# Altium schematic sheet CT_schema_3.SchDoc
size 300 x 247 mm
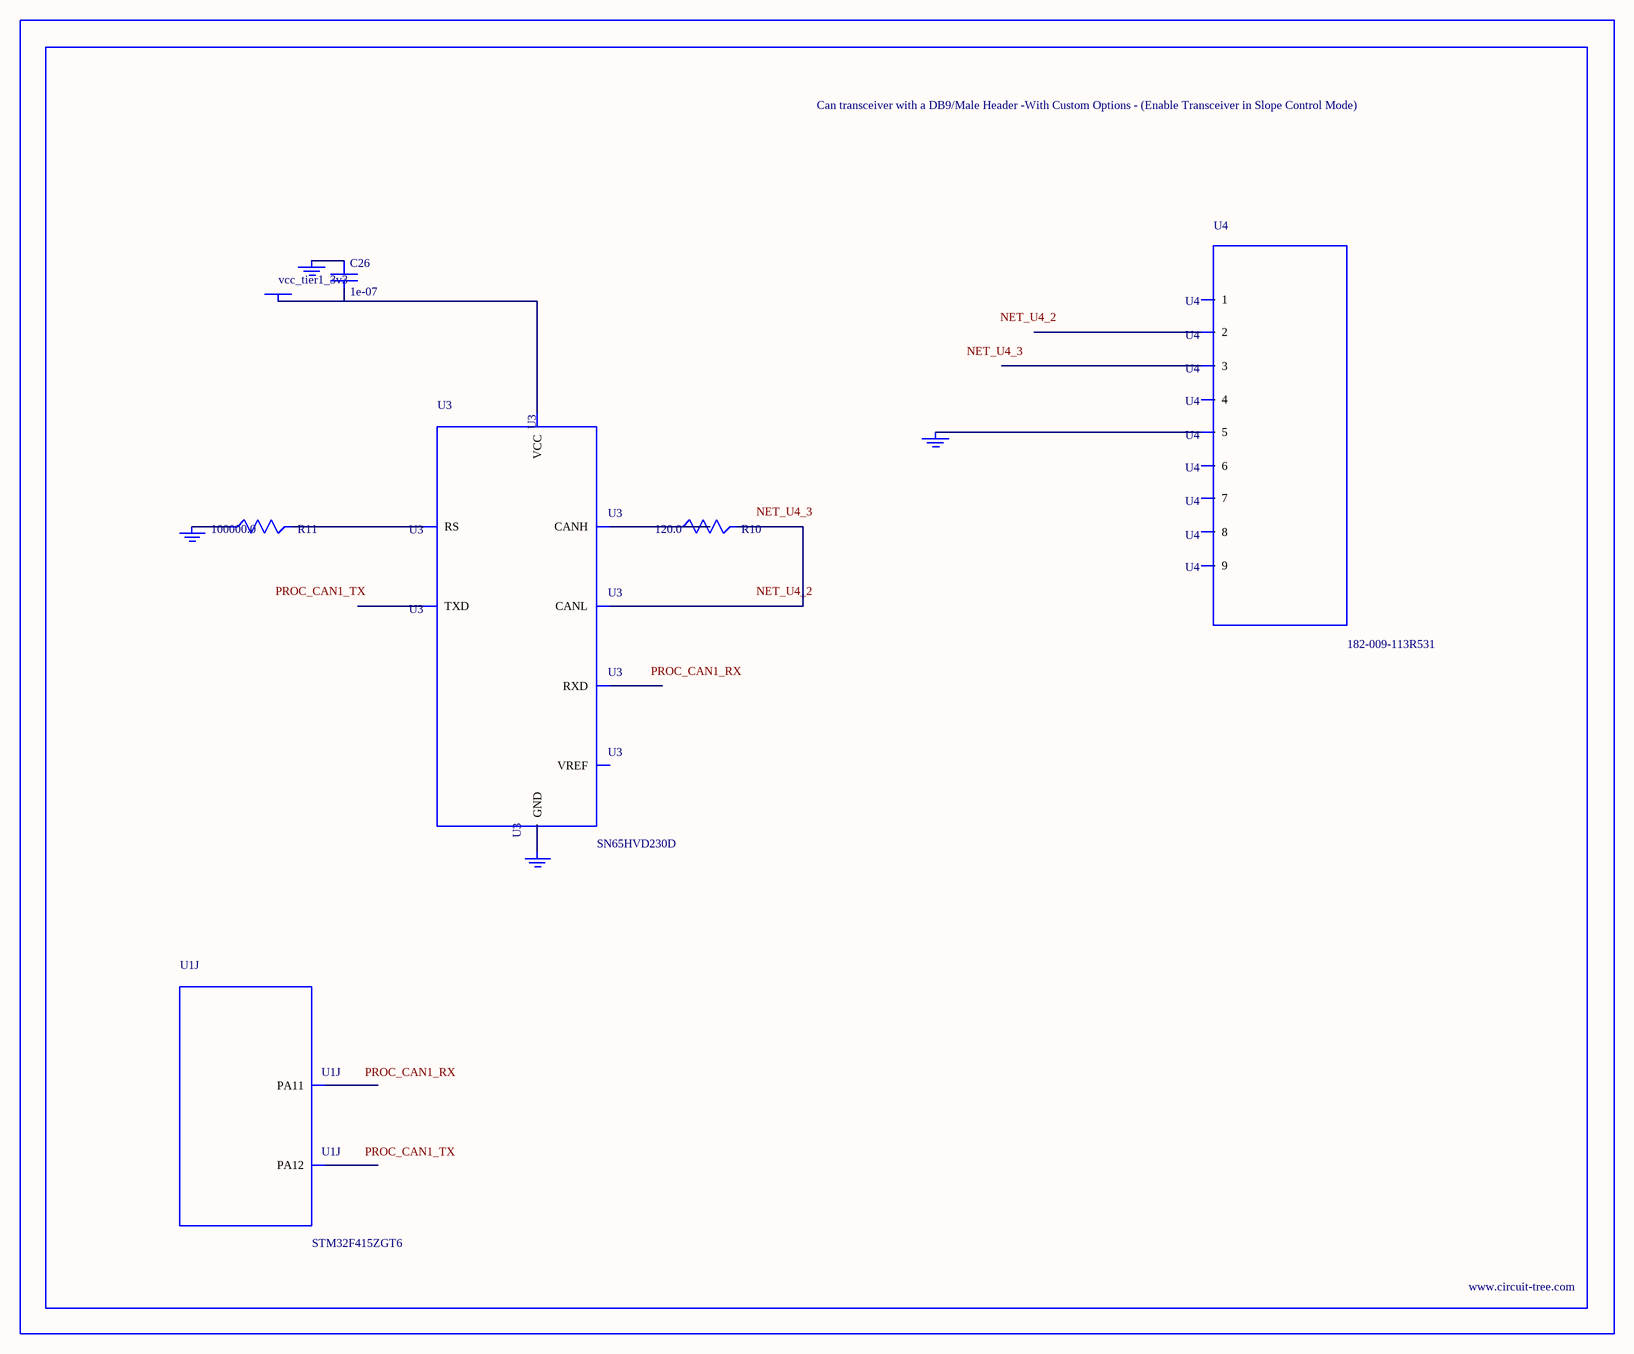
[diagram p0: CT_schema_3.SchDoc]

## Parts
BORDER2  (no value)
C26  1e-07  [C0402]
GND_INSTANCE_2_0  (no value)
GND_INSTANCE_2_1  (no value)
GND_INSTANCE_2_2  (no value)
GND_INSTANCE_2_3  (no value)
POWER_INSTANCE_2_0  vcc_tier1_3v3
R10  120.0  [R0603]
R11  100000.0  [R0603]
U1  STM32F415ZGT6  [LQFP144]  (part J of 12)
U3  SN65HVD230D  [SOIC-8]
U4  182-009-113R531  [182-009-MALE]

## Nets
NetC26_1: C26.1 GND_INSTANCE_2_0.0(GND)
NetC26_2: C26.2 POWER_INSTANCE_2_0.0(PWR) U3.3(VCC)
NetGND_INSTANCE_2_1_0: GND_INSTANCE_2_1.0(GND) R11.1
NetGND_INSTANCE_2_2_0: GND_INSTANCE_2_2.0(GND) U3.2(GND)
NetGND_INSTANCE_2_3_0: GND_INSTANCE_2_3.0(GND) U4.5
NetR10_1: R10.1 U3.7(CANH)
NetR10_2: R10.2 U3.6(CANL)
NetR11_2: R11.2 U3.8(RS)

Not connected (* = marked no-connect by the designer): U1 103(PA11) 104(PA12); U3 1(TXD) 4(RXD) 5(VREF); U4 1 2 3 4 6 7 8 9

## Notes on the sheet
- Labels drawn without touching a wire or pin: NET_U4_2, NET_U4_3, PROC_CAN1_RX, PROC_CAN1_TX

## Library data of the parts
BORDER2 = BORDER_PAGE2
C26 = C0402C104K3RACTU
GND_INSTANCE_2_0-GND_INSTANCE_2_3 = GND
POWER_INSTANCE_2_0 = PWR
R10 = RC0603JR-07120RL
R11 = RC0603JR-07100KL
